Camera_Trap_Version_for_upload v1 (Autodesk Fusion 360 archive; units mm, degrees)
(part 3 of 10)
sketch "Sketch1" plane through (0, 50, 0) normal (0, 1, 0) x axis (-1, 0, 0)
  line L1 (19, 40.6) -> (11, 40.6)
  line L2 (19, 163.6063) -> (19, 40.6)
  line L3 (32, 163.6063) -> (19, 163.6063)
  line L4 (37, 215) -> (37, 168.6063)
  line L5 (30, 215) -> (37, 215)
  line L6 (30, 175.6063) -> (30, 215)
  line L7 (11, 170.6063) -> (25, 170.6063)
  line L8 (11, 40.6) -> (11, 170.6063)
  line L9 (37, 215) -> (37, 168.6063)
  line L10 (32, 163.6063) -> (19, 163.6063)
  line L11 (19, 40.6) -> (19, 163.6063)
  line L12 (-126.7143, 211.7174) -> (-122, 215)
  line L13 (-129, 215) -> (-126.7143, 211.7174)
  line L14 (19, 215) -> (-129, 215)
  line L15 (19, 40.6) -> (19, 215)
  line L16 (-129, 40.6) -> (19, 40.6)
  line L17 (-129, 215) -> (-129, 40.6)
  line L18 (19, 215) -> (37, 215)
  line L19 (19, 163.6063) -> (19, 215)
  line L20 (37, 168.6018) -> (37, 215)
  line L21 (19, 163.6063) -> (31.9982, 163.6018)
  line L22 (-102.2935, 219) -> (-102.2935, 215)
  arc A1 centre (32, 168.6063) radius 5 clockwise from (37, 168.6063) to (32, 163.6063)
  arc A2 centre (25, 175.6063) radius 5 clockwise from (30, 175.6063) to (25, 170.6063)
  arc A3 centre (32, 168.6063) radius 5 clockwise from (37, 168.6063) to (32, 163.6063)
  arc A4 centre (32, 168.6018) radius 5 clockwise from (37, 168.6018) to (31.9982, 163.6018)
  point P20 (19, 40.6)
  point P25 (19, 40.6)
  point P8 (37, 215)
  point P27 (37, 215)
  point P28 (19, 215)
  point P4 (19, 163.6063)
  point P29 (19, 163.6063)
  point P30 (37, 163.6)
  point P34 (-102.2935, 215)
  point P22 (-126.7143, 211.7174)
  point P23 (-129, 215)
  point P35 (-102.2935, 219)
  perpendicular L12 L13
  horizontal L14
  vertical L15
  horizontal L16
  vertical L17
  coincident P20 P25
  coincident P8 P27
  coincident L15 P28
  perpendicular L15 L18
  coincident P4 P29
  perpendicular L18 L20
  coincident P30 L20
  coincident P30 L21
  tangent L20 A4
  tangent L21 A4
  coincident L14 P34
  perpendicular L14 L22
  dimension "d509" distance P22 P23 = 4
  dimension "d510" distance P27 P30 = 51.4
  dimension "d511" radius A4 = 5
  dimension "d514" distance P34 P35 = 4
extrude "Extrude1" new body sketch "Sketch1" profile of L1 L2 L3 L5 L6 A2 L7 L8 L9 A3 L11 L14 L15 L16 L17 L18 L19 L20 along normal blind 7
sketch "Sketch1" plane through (129, 0, 0) normal (1, 0, 0) x axis (0, 1, 0)
  line L1 (50, 40.6) -> (50, 215)
  line L2 (57, 40.6) -> (50, 40.6)
  line L3 (57, 215) -> (57, 40.6)
  line L4 (50, 215) -> (57, 215)
  line L5 (0, 220) -> (0, 40)
  line L6 (-50, 170.6) -> (-50, 60.6)
  line L7 (-30, 40.6) -> (50, 40.6)
  line L8 (57, 40.6) -> (57, 215)
  line L9 (57, 40.6) -> (50, 40.6)
  line L10 (50, 215) -> (-50, 215)
  line L11 (-50, 215) -> (-50, 175.6063)
  line L12 (-50, 170.6063) -> (-50, 175.6063)
  line L13 (-25, 40.6) -> (57, 40.6)
  line L14 (-50, 220.6) -> (-50, 65.6)
  line L15 (57, 220.6) -> (-50, 220.6)
  line L16 (57, 40.6) -> (57, 220.6)
  line L17 (15, 95.6) -> (-15, 95.6)
  line L18 (25, 55.6) -> (25, 85.6)
  line L19 (-15, 45.6) -> (15, 45.6)
  line L20 (-25, 85.6) -> (-25, 55.6)
  circle C1 centre (0, 195.4) radius 20
  arc A1 centre (-30, 60.6) radius 20 clockwise from (-30, 40.6) to (-50, 60.6)
  arc A2 centre (-25, 65.6) radius 25 clockwise from (-25, 40.6) to (-50, 65.6)
  circle C2 centre (0, 70.6) radius 11
  arc A3 centre (-15, 85.6) radius 10 clockwise from (-25, 85.6) to (-15, 95.6)
  arc A4 centre (15, 85.6) radius 10 clockwise from (15, 95.6) to (25, 85.6)
  arc A5 centre (15, 55.6) radius 10 clockwise from (25, 55.6) to (15, 45.6)
  arc A6 centre (-15, 55.6) radius 10 clockwise from (-15, 45.6) to (-25, 55.6)
  point P4 (57, 40.6)
  point P21 (57, 40.6)
  point P23 (57, 220.6)
  vertical L5
  horizontal L13
  vertical L14
  horizontal L15
  vertical L16
  coincident P4 P21
  tangent L13 A2
  tangent L14 A2
  dimension "d515" distance P21 P23 = 180
  dimension "d516" radius A2 = 25
extrude "Extrude1" new body sketch "Sketch1" profile of L1 L2 L3 L4 C1 L6 L7 L8 L9 L10 L11 L12 L13 L14 L15 L16 A2 along normal blind 7
extrude "Extrude7" cut of existing geometry blind -7
sketch "Sketch2" plane through (-5, 0, 0) normal (1, 0, 0) x axis (0, 1, 0)
  circle C1 centre (0, 70.6) radius 11.1
  circle C2 centre (0, 70.6) radius 13.1
extrude "Extrude3" cut of existing geometry blind -10
extrude "Extrude4" cut sketch "Sketch1" profile of C8 C9 C10 C11 against normal blind 10
combine "Combine1"
sketch "Sketch1" plane through (0, -50, 0) normal (0, -1, 0) x axis (1, 0, 0)
  line L1 (129, 65.6) -> (129, 220.6)
  line L2 (136, 65.6) -> (129, 65.6)
  line L3 (136, 220.6) -> (136, 65.6)
  line L4 (129, 220.6) -> (136, 220.6)
  line L5 (-14, 139) -> (-19, 139)
  line L6 (-14, 129) -> (-14, 139)
  line L7 (-19, 129) -> (-14, 129)
  line L8 (-19, 139) -> (-19, 129)
  line L9 (131, 139) -> (131, 129)
  line L10 (131, 129) -> (136, 129)
  line L11 (136, 129) -> (136, 139)
  line L12 (136, 139) -> (131, 139)
  horizontal L5
  vertical L6
  horizontal L7
  vertical L8
  horizontal L12
  vertical L11
  horizontal L10
  vertical L9
extrude "Extrude1" new body sketch "Sketch1" profile of L3 L5 L6 L7 L8 L9 L10 L11 L12 along normal blind 8
chamfer "Chamfer1" distance 1
chamfer "Chamfer2" distance 1
combine "Combine1"
fillet "Fillet1" radius 10
fillet "Fillet2" radius 10
sketch "Sketch1" plane through (0, -50, 0) normal (0, -1, 0) x axis (1, 0, 0)
  line L1 (-19, 129) -> (-14, 129)
  line L2 (-19, 60.6) -> (-19, 129)
  line L3 (-11, 60.6) -> (-19, 60.6)
  line L4 (-11, 170.6063) -> (-11, 60.6)
  line L5 (-25, 170.6063) -> (-11, 170.6063)
  line L6 (-30, 215) -> (-30, 175.6063)
  line L7 (-37, 215) -> (-30, 215)
  line L8 (-37, 168.6063) -> (-37, 215)
  line L9 (-19, 163.6063) -> (-32, 163.6063)
  line L10 (-19, 139) -> (-19, 163.6063)
  line L11 (-14, 139) -> (-19, 139)
  line L12 (-14, 129) -> (-14, 139)
  line L13 (131, 129) -> (136, 129)
  line L14 (131, 139) -> (131, 129)
  line L15 (136, 139) -> (131, 139)
  line L16 (136, 220.6) -> (136, 139)
  line L17 (129, 220.6) -> (136, 220.6)
  line L18 (129, 65.6) -> (129, 220.6)
  line L19 (136, 65.6) -> (129, 65.6)
  line L20 (136, 129) -> (136, 65.6)
  line L21 (141.4511, 160) -> (-25, 160)
  line L22 (141.4511, 105) -> (141.4511, 160)
  line L23 (-25, 105) -> (141.4511, 105)
  line L24 (-25, 160) -> (-25, 105)
  line L25 (-13.6, 139) -> (-19, 139)
  line L26 (-13.6, 129) -> (-13.6, 139)
  line L27 (-19, 129) -> (-13.6, 129)
  line L28 (-19, 139) -> (-19, 129)
  line L29 (130.6, 139) -> (136, 139)
  line L30 (130.6, 129) -> (130.6, 139)
  line L31 (136, 129) -> (130.6, 129)
  line L32 (136, 139) -> (136, 129)
  line L33 (129, 160) -> (141.4511, 160)
  line L34 (125, 160) -> (141.4511, 160)
  arc A1 centre (-25, 175.6063) radius 5 clockwise from (-25, 170.6063) to (-30, 175.6063)
  arc A2 centre (-32, 168.6063) radius 5 clockwise from (-32, 163.6063) to (-37, 168.6063)
  point P16 (-19, 139)
  point P30 (-19, 139)
  point P21 (136, 139)
  point P34 (136, 139)
  point P38 (129, 160)
  point P39 (125, 160)
  point P40 (125, 160)
  point P41 (10, 160)
  point P31 (-13.6, 139)
  point P35 (130.6, 139)
  horizontal L21
  vertical L22
  horizontal L23
  vertical L24
  horizontal L25
  vertical L26
  horizontal L27
  vertical L28
  coincident P16 P30
  horizontal L29
  vertical L30
  horizontal L31
  vertical L32
  coincident P21 P34
  coincident L18 P38
  coincident L21 P38
  coincident L21 P39
  perpendicular L18 L34
  coincident P39 P40
  coincident L21 P41
  dimension "d535" distance P30 P31 = 5.4
  dimension "d536" distance P34 P35 = 5.4
extrude "Extrude1" new body sketch "Sketch1" profile of L1 L2 L4 L10 L11 L13 L15 L16 L18 L20 L21 L22 L23 L24 L25 L26 L27 L28 L29 L30 L31 L32 along normal blind 7 bodies "Front_wall"
fillet "Fillet1" radius 7
fillet "Fillet2" radius 7
copy_paste_bodies "CopyPasteBodies1"
copy_paste "CopyPaste10"
sketch "LL_pin" plane through (0, 0, 0) normal (0, 1, 0) x axis (1, 0, 0)
  line L1 (200, 0) -> (-200, 0)
  line L2 (0, -70) -> (0, 0)
  line L3 (-11, -70) -> (5, -70)
  line L4 (-11, -74.1) -> (-11, -70)
  line L5 (5, -70) -> (5, -74.1)
  line L6 (-5, -70) -> (-3, -70)
  line L7 (-5, -75) -> (-5, -74.1)
  line L8 (-3, -75) -> (-5, -75)
  line L9 (-3, -74.1) -> (-3, -75)
  line L10 (-5, -74.1) -> (-11, -74.1)
  line L11 (5, -74.1) -> (-3, -74.1)
  point P1 (0, 0)
  point P4 (0, 0)
  point P10 (-3, -70)
  point P2 (-200, 0)
  point P3 (200, 0)
  point P5 (0, -70)
  point P6 (5, -70)
  point P7 (-11, -70)
  point P9 (5, -74.1)
  point P11 (-5, -70)
  point P13 (-3, -75)
  horizontal L1
  coincident P1 P4
  perpendicular L1 L2
  horizontal L3
  vertical L4
  horizontal L10
  vertical L5
  horizontal L6
  vertical L7
  horizontal L8
  vertical L9
  midpoint L3 P10
  collinear L10 L11
  dimension "d120_4" distance P2 P3 = 400
  dimension "d122_4" distance P4 P5 = 70
  dimension "d123_4" distance P6 P7 = 16 (= "LL_Pin_Length")
  dimension "d124_4" distance P6 P9 = 4.1 (= "LL_Pin_half_height")
  dimension "d129_4" distance P10 P11 = 2 (= "LL_lip_length")
  dimension "d130_4" distance P10 P13 = 5 (= "LL_lip_half_height")
revolve "Revolve1" sketch "LL_pin" AlongAngle 360 named "d131_4" bodies "S1_L_Pin"
sketch "LL_pin_falt_face" plane through (5, 0, 0) normal (1, 0, 0) x axis (0, 1, 0)
  line L1 (0, 67) -> (0, 70)
  line L2 (2.8039, 67.0087) -> (-2.8039, 67.0087)
  circle C1 centre (0, 70) radius 4.1
  point P2 (0, 70)
  point P3 (0, 70)
  point P5 (-2.8039, 67.0087)
  point P6 (2.8039, 67.0087)
  coincident P2 P3
  vertical L1
  coincident C1 P5
  coincident C1 P6
  perpendicular L1 L2
extrude "Extrude1" cut sketch "LL_pin_falt_face" profile of C1 L2 against normal blind 5 named "d132_4"
fillet "Fillet1" radius 1 named "d135_3"
position "Position12"
position "Position13"
extrude "Extrude2" add of existing geometry blind 67
work_plane "WorkPlane1" RotateAngle 0
sketch "Sketch5" plane through (0, 0, 0) normal (0, 1, 0) x axis (1, 0, 0)
  line L1 (-78, -74.1) -> (-78, -65.9)
  line L2 (0, -67.0087) -> (0, -65.9)
  line L3 (5, -67.0087) -> (0, -67.0087)
  line L4 (5, -74.1) -> (5, -67.0087)
  line L5 (-5, -65.9) -> (-5, -65)
  line L6 (-5, -75) -> (-5, -74.1)
  line L7 (-2.005, -65.9) -> (0, -65.9)
  line L8 (-2.005, -74.1) -> (5, -74.1)
  line L9 (-5, -65) -> (-3, -65)
  line L10 (-5, -75) -> (-3, -75)
  line L11 (-78, -65.9) -> (-5, -65.9)
  line L12 (-78, -74.1) -> (-5, -74.1)
  line L13 (-41, -75) -> (-5, -75)
  line L14 (-63, -75) -> (-41, -75)
  line L15 (-68, -75) -> (-63, -75)
  line L16 (-41, -75) -> (-63, -75)
  line L17 (-41, -65) -> (-41, -75)
  line L18 (-63, -65) -> (-41, -65)
  line L19 (-63, -75) -> (-63, -65)
  line L20 (-73, -75) -> (-74, -75)
  line L21 (-73, -65) -> (-73, -75)
  line L22 (-74, -65) -> (-73, -65)
  line L23 (-74, -75) -> (-74, -65)
  arc A1 centre (-2.005, -75.1) radius 1 clockwise from (-3, -75) to (-2.005, -74.1)
  arc A2 centre (-2.005, -64.9) radius 1 clockwise from (-2.005, -65.9) to (-3, -65)
  point P11 (-5, -75)
  point P18 (-5, -75)
  point P19 (-41, -75)
  point P20 (-63, -75)
  point P21 (-68, -75)
  point P25 (-74, -75)
  point P26 (-73, -75)
  coincident P11 P18
  perpendicular L6 L13
  parallel L12 L14
  parallel L14 L15
  horizontal L16
  vertical L17
  horizontal L18
  vertical L19
  horizontal L20
  vertical L21
  horizontal L22
  vertical L23
  dimension "d546" distance P18 P19 = 36
  dimension "d547" distance P19 P20 = 22
  dimension "d548" distance P20 P21 = 5
  dimension "d549" distance P25 P26 = 1
extrude "Extrude3" cut sketch "Sketch5" profile of L11 L12 L17 L18 L19 distance 0.5
revolve "Revolve2" sketch "Sketch5" AlongAngle 360
sketch "Roll_holders" plane through (0, 0, 0) normal (0, 1, 0) x axis (1, 0, 0)
  curve K1 (-18.5, -200.1) -> (-16.5, -200.1)
  curve K2 (-16.5, -191.9) -> (-18.5, -191.9)
  line L1 (-21, -200.1) -> (-21, -191.9)
  line L2 (5, -193.0087) -> (-3, -193.0087)
  line L3 (5, -200.1) -> (5, -193.0087)
  line L4 (-5, -191.9) -> (-5, -191)
  line L5 (-5, -201) -> (-5, -200.1)
  line L6 (-5, -191) -> (-3, -191)
  line L7 (-5, -201) -> (-3, -201)
  line L8 (-16.5, -191.9) -> (-5, -191.9)
  line L9 (-21, -191.9) -> (-18.5, -191.9)
  line L10 (-16.5, -200.1) -> (-5, -200.1)
  line L11 (-21, -200.1) -> (-18.5, -200.1)
  line L12 (0, -227.8815) -> (0, -227.7827)
  line L13 (0, -227.7827) -> (0, -227.4397)
  line L14 (0, -227.4397) -> (0, -227.2429)
  line L15 (0, -227.2429) -> (0, -226.6752)
  line L16 (0, -227.9963) -> (0, -227.8815)
  line L17 (0, -228) -> (0, -227.9963)
  line L18 (0, -164.0037) -> (0, -164)
  line L19 (0, -164.0037) -> (0, -164.1185)
  line L20 (0, -164.2173) -> (0, -164.1185)
  line L21 (0, -164.2173) -> (0, -164.5603)
  line L22 (0, -164.7571) -> (0, -164.5603)
  line L23 (0, -164.7571) -> (0, -165.3248)
  line L24 (0, -165.6174) -> (0, -165.3248)
  line L25 (0, -165.6174) -> (0, -166.4041)
  line L26 (0, -166.7895) -> (0, -166.4041)
  line L27 (0, -166.7895) -> (0, -167.787)
  line L28 (0, -168.2613) -> (0, -167.787)
  line L29 (0, -168.2613) -> (0, -169.4595)
  line L30 (0, -170.0178) -> (0, -169.4595)
  line L31 (0, -170.0178) -> (0, -171.4042)
  line L32 (0, -172.0409) -> (0, -171.4042)
  line L33 (0, -172.0409) -> (0, -173.6014)
  line L34 (0, -174.3098) -> (0, -173.6014)
  line L35 (0, -174.3098) -> (0, -176.0032)
  line L36 (0, -176.0032) -> (0, -176.0038)
  line L37 (0, -176.0038) -> (0, -176.0284)
  line L38 (0, -176.8013) -> (0, -176.0284)
  line L39 (0, -176.8013) -> (0, -178.3701)
  line L40 (0, -178.3701) -> (0, -178.3707)
  line L41 (0, -178.3707) -> (0, -178.5249)
  line L42 (0, -178.6604) -> (0, -178.5249)
  line L43 (0, -179.4899) -> (0, -178.6604)
  line L44 (0, -179.4899) -> (0, -180.918)
  line L45 (0, -180.918) -> (0, -180.9184)
  line L46 (0, -180.9184) -> (0, -181.0503)
  line L47 (0, -181.4703) -> (0, -181.0503)
  line L48 (0, -182.3478) -> (0, -181.4703)
  line L49 (0, -182.3478) -> (0, -183.6205)
  line L50 (0, -183.6205) -> (0, -183.6209)
  line L51 (0, -183.6209) -> (0, -183.7292)
  line L52 (0, -184.4292) -> (0, -183.7292)
  line L53 (0, -185.3458) -> (0, -184.4292)
  line L54 (0, -185.3458) -> (0, -186.4501)
  line L55 (0, -186.4501) -> (0, -186.4504)
  line L56 (0, -186.4504) -> (0, -186.534)
  line L57 (0, -187.4694) -> (0, -186.534)
  line L58 (0, -187.507) -> (0, -187.4694)
  line L59 (0, -188.4532) -> (0, -187.507)
  line L60 (0, -188.4532) -> (0, -189.3777)
  line L61 (0, -189.3777) -> (0, -189.3779)
  line L62 (0, -189.3779) -> (0, -189.4359)
  line L63 (0, -190.5109) -> (0, -189.4359)
  line L64 (0, -190.6718) -> (0, -190.5109)
  line L65 (0, -191.6379) -> (0, -190.6718)
  line L66 (0, -191.6379) -> (0, -192.3733)
  line L67 (0, -192.3733) -> (0, -192.3734)
  line L68 (0, -192.3734) -> (0, -192.4051)
  line L69 (0, -193.5524) -> (0, -192.4051)
  line L70 (0, -193.8913) -> (0, -193.5524)
  line L71 (0, -194.8675) -> (0, -193.8913)
  line L72 (0, -194.8675) -> (0, -195.4061)
  line L73 (0, -195.4061) -> (0, -195.4061)
  line L74 (0, -195.4061) -> (0, -195.4113)
  line L75 (0, -196.5887) -> (0, -195.4113)
  line L76 (0, -196.5939) -> (0, -196.5887)
  line L77 (0, -196.5939) -> (0, -196.5939)
  line L78 (0, -197.1325) -> (0, -196.5939)
  line L79 (0, -198.1087) -> (0, -197.1325)
  line L80 (0, -198.1087) -> (0, -198.4476)
  line L81 (0, -199.5949) -> (0, -198.4476)
  line L82 (0, -199.6266) -> (0, -199.5949)
  line L83 (0, -199.6267) -> (0, -199.6266)
  line L84 (0, -200.3621) -> (0, -199.6267)
  line L85 (0, -201.3282) -> (0, -200.3621)
  line L86 (0, -201.3282) -> (0, -201.4891)
  line L87 (0, -202.5641) -> (0, -201.4891)
  line L88 (0, -202.6221) -> (0, -202.5641)
  line L89 (0, -202.6223) -> (0, -202.6221)
  line L90 (0, -203.5468) -> (0, -202.6223)
  line L91 (0, -204.493) -> (0, -203.5468)
  line L92 (0, -204.493) -> (0, -204.5306)
  line L93 (0, -205.466) -> (0, -204.5306)
  line L94 (0, -205.5496) -> (0, -205.466)
  line L95 (0, -205.5499) -> (0, -205.5496)
  line L96 (0, -206.6542) -> (0, -205.5499)
  line L97 (0, -207.5708) -> (0, -206.6542)
  line L98 (0, -208.2708) -> (0, -207.5708)
  line L99 (0, -208.3791) -> (0, -208.2708)
  line L100 (0, -208.3795) -> (0, -208.3791)
  line L101 (0, -209.6522) -> (0, -208.3795)
  line L102 (0, -210.5297) -> (0, -209.6522)
  line L103 (0, -210.9497) -> (0, -210.5297)
  line L104 (0, -211.0816) -> (0, -210.9497)
  line L105 (0, -211.082) -> (0, -211.0816)
  line L106 (0, -212.5101) -> (0, -211.082)
  line L107 (0, -213.3396) -> (0, -212.5101)
  line L108 (0, -213.4751) -> (0, -213.3396)
  line L109 (0, -213.6293) -> (0, -213.4751)
  line L110 (0, -213.6299) -> (0, -213.6293)
  line L111 (0, -215.1987) -> (0, -213.6299)
  line L112 (0, -215.9716) -> (0, -215.1987)
  line L113 (0, -215.9962) -> (0, -215.9716)
  line L114 (0, -215.9968) -> (0, -215.9962)
  line L115 (0, -217.6902) -> (0, -215.9968)
  line L116 (0, -218.3986) -> (0, -217.6902)
  line L117 (0, -219.9591) -> (0, -218.3986)
  line L118 (0, -220.5958) -> (0, -219.9591)
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  point P279 (6, -196)
  point P283 (21, -196)
  point P285 (6, -216)
  point P280 (21, -196)
  point P286 (26, -196)
  point P288 (21, -211)
  point P287 (26, -211)
  point P289 (44.1262, -202.5476)
  point P292 (122, -196)
  point P293 (117, -196)
  point P295 (122, -211)
  point P294 (117, -211)
  point P296 (98.8738, -202.5477)
  point P298 (127, -196)
  point P300 (122, -216)
  dimension "d335_1" distance P279 P283 = 15
  dimension "d336_1" distance P279 P285 = 20
  dimension "d337_1" distance P280 P286 = 5
  dimension "d338_1" distance P280 P288 = 15
  dimension "d339_1" angle = 25
  dimension "d340_1" distance P287 P289 = 20
  dimension "d342_1" distance P283 P292 = 101
  dimension "d343_1" distance P292 P293 = 5
  dimension "d344_1" distance P292 P295 = 15
  dimension "d345_1" angle = 155
  dimension "d346_1" distance P294 P296 = 20
  dimension "d347_1" distance P292 P298 = 5
  dimension "d348_1" distance P292 P300 = 20
revolve "Revolve1" sketch "Roll_holders" AlongAngle 360 named "d341_1"
position "Position14"
extrude "Extrude1" add of existing geometry blind 3
sketch "LL_pin" plane through (0, 0, 0) normal (0, 1, 0) x axis (1, 0, 0)
  line L1 (200, 0) -> (-200, 0)
  line L2 (0, -70) -> (0, 0)
  line L3 (-11, -70) -> (5, -70)
  line L4 (-11, -74.1) -> (-11, -70)
  line L5 (5, -70) -> (5, -74.1)
  line L6 (-5, -70) -> (-3, -70)
  line L7 (-5, -75) -> (-5, -74.1)
  line L8 (-3, -75) -> (-5, -75)
  line L9 (-3, -74.1) -> (-3, -75)
  line L10 (-5, -74.1) -> (-11, -74.1)
  line L11 (5, -74.1) -> (-3, -74.1)
  point P1 (0, 0)
  point P4 (0, 0)
  point P10 (-3, -70)
  point P2 (-200, 0)
  point P3 (200, 0)
  point P5 (0, -70)
  point P6 (5, -70)
  point P7 (-11, -70)
  point P9 (5, -74.1)
  point P11 (-5, -70)
  point P13 (-3, -75)
  horizontal L1
  coincident P1 P4
  perpendicular L1 L2
  horizontal L3
  vertical L4
  horizontal L10
  vertical L5
  horizontal L6
  vertical L7
  horizontal L8
  vertical L9
  midpoint L3 P10
  collinear L10 L11
  dimension "d120_5" distance P2 P3 = 400
  dimension "d122_5" distance P4 P5 = 70
  dimension "d123_5" distance P6 P7 = 16 (= "LL_Pin_Length")
  dimension "d124_5" distance P6 P9 = 4.1 (= "LL_Pin_half_height")
  dimension "d129_5" distance P10 P11 = 2 (= "LL_lip_length")
  dimension "d130_5" distance P10 P13 = 5 (= "LL_lip_half_height")
revolve "Revolve1" sketch "LL_pin" AlongAngle 360 named "d131_5" bodies "S1_L_Pin"
sketch "LL_pin_falt_face" plane through (5, 0, 0) normal (1, 0, 0) x axis (0, 1, 0)
  line L1 (0, 67) -> (0, 70)
  line L2 (2.8039, 67.0087) -> (-2.8039, 67.0087)
  circle C1 centre (0, 70) radius 4.1
  point P2 (0, 70)
  point P3 (0, 70)
  point P5 (-2.8039, 67.0087)
  point P6 (2.8039, 67.0087)
  coincident P2 P3
  vertical L1
  coincident C1 P5
  coincident C1 P6
  perpendicular L1 L2
extrude "Extrude1" cut sketch "LL_pin_falt_face" profile of C1 L2 against normal blind 5 named "d132_5"
fillet "Fillet1" radius 1 named "d135_4"
sketch "paper_holder" plane through (0, 0, 0) normal (0, 1, 0) x axis (1, 0, 0)
  line L1 (16, -74.1) -> (16, -77.5)
  line L2 (11, -74.1) -> (16, -74.1)
  line L3 (11, -70) -> (11, -74.1)
  line L4 (127, -75) -> (129, -75)
  line L5 (127, -77.5) -> (127, -75)
  line L6 (16, -77.5) -> (127, -77.5)
  line L7 (135, -74.1) -> (135, -70)
  line L8 (129, -74.1) -> (135, -74.1)
  line L9 (129, -75) -> (129, -74.1)
  line L10 (150, -70) -> (140, -70)
  line L11 (135, -70) -> (11, -70)
  line L12 (21, -74.1) -> (16, -74.1)
  line L13 (122, -69) -> (122, -71)
  line L14 (21, -71) -> (21, -69)
  line L15 (122, -80) -> (21, -80)
  line L16 (122, -62.5) -> (122, -80)
  line L17 (21, -62.5) -> (122, -62.5)
  line L18 (21, -80) -> (21, -62.5)
  point P2 (16, -77.5)
  point P3 (16, -74.1)
  point P4 (11, -74.1)
  point P5 (129, -75)
  point P6 (127, -75)
  point P7 (127, -77.5)
  point P15 (21, -71)
  point P16 (122, -71)
  point P19 (21, -80)
  point P20 (122, -80)
  point P22 (21, -62.5)
  vertical L1
  perpendicular L1 L2
  perpendicular L2 L3
  perpendicular L4 L5
  parallel L8 L10
  perpendicular L1 L12
  vertical L13
  vertical L14
  horizontal L15
  vertical L16
  horizontal L17
  vertical L18
  dimension "d146_2" distance P2 P3 = 3.4
  dimension "d147_2" distance P3 P4 = 5
  dimension "d154_2" distance P5 P6 = 2
  dimension "d155_2" distance P6 P7 = 2.5
  dimension "d164_2" distance P15 P16 = 101
  dimension "d167_2" distance P19 P20 = 101
  dimension "d168_2" distance P19 P22 = 17.5
move "Move2"
sketch "Sketch5" plane through (486.5, 0, 0) normal (1, 0, 0) x axis (0, 1, 0)
  line L1 (0.1129, -15.3996) -> (0.1129, -17.3996)
  line L2 (8.1247, -15.3996) -> (0.1129, -15.3996)
  line L3 (-8.1247, -15.3996) -> (0.1129, -15.3996)
  circle C1 centre (0, 0.1) radius 4.1
  circle C2 centre (0, 0.1) radius 17.5
  point P3 (0.1129, -17.3996)
  point P5 (8.1247, -15.3996)
  point P6 (-8.1247, -15.3996)
  point P4 (0.1129, -15.3996)
  coincident C2 P3
  vertical L1
  coincident C2 P5
  perpendicular L1 L2
  coincident C2 P6
  perpendicular L1 L3
  dimension "d560" distance P3 P4 = 2
copy_paste_bodies "CopyPasteBodies2"
move "Move2"
move "Move3"
sketch "LL_pin" plane through (0, 0, 0) normal (0, 1, 0) x axis (1, 0, 0)
  line L1 (200, 0) -> (-200, 0)
  line L2 (0, -70) -> (0, 0)
  line L3 (-11, -70) -> (5, -70)
  line L4 (-11, -74.1) -> (-11, -70)
  line L5 (-5, -70) -> (-3, -70)
  line L6 (-5, -75) -> (-5, -74.1)
  line L7 (-4, -75) -> (-5, -75)
  line L8 (-5, -74.1) -> (-11, -74.1)
  line L9 (5, -74.1) -> (-1, -74.1)
  line L10 (-3, -75) -> (-3, -74.1)
  line L11 (-2, -74.1) -> (-1, -74.1)
  line L12 (-4, -83) -> (-2, -83)
  line L13 (-4, -75) -> (-4, -83)
  line L14 (-2, -74.1) -> (-2, -83)
  line L15 (7, -74.1) -> (5, -74.1)
  line L16 (7, -70) -> (7, -74.1)
  line L17 (5, -70) -> (7, -70)
  point P1 (0, 0)
  point P4 (0, 0)
  point P10 (-3, -70)
  point P2 (-200, 0)
  point P3 (200, 0)
  point P5 (0, -70)
  point P6 (5, -70)
  point P7 (-11, -70)
  point P9 (5, -74.1)
  point P11 (-5, -70)
  point P13 (-3, -75)
  horizontal L1
  coincident P1 P4
  perpendicular L1 L2
  horizontal L3
  vertical L4
  horizontal L8
  horizontal L5
  vertical L6
  horizontal L7
  midpoint L3 P10
  collinear L8 L9
  perpendicular L7 L10
  parallel L9 L11
  horizontal L12
  perpendicular L11 L14
  perpendicular L15 L16
  dimension "d120_3_1_1" distance P2 P3 = 400
  dimension "d122_3_1_1" distance P4 P5 = 70
  dimension "d123_3_1_1" distance P6 P7 = 16 (= "LL_Pin_Length")
  dimension "d124_3_1_1" distance P6 P9 = 4.1 (= "LL_Pin_half_height")
  dimension "d129_3_1_1" distance P10 P11 = 2 (= "LL_lip_length")
  dimension "d130_3_1_1" distance P10 P13 = 5 (= "LL_lip_half_height")
revolve "Revolve1" sketch "LL_pin" AlongAngle 360 named "d131_3_1_1" bodies "S2_L_Pin"
sketch "LL_pin_falt_face" plane through (5, 0, 0) normal (1, 0, 0) x axis (0, 1, 0)
  line L1 (0, 67) -> (0, 70)
  line L2 (2.8039, 67.0087) -> (-2.8039, 67.0087)
  circle C1 centre (0, 70) radius 4.1
  point P2 (0, 70)
  point P3 (0, 70)
  point P5 (-2.8039, 67.0087)
  point P6 (2.8039, 67.0087)
  coincident P2 P3
  vertical L1
  coincident C1 P5
  coincident C1 P6
  perpendicular L1 L2
extrude "Extrude1" cut sketch "LL_pin_falt_face" profile of C1 L2 against normal blind 5 named "d132_3_1_1"
position "Position16"
position "Position17"
extrude "Extrude2" add of existing geometry blind 2
extrude "Extrude3" cut sketch "LL_pin_falt_face" profile of C1 L2 along normal blind 2
fillet "Fillet2" radius 1
position "Position18"
extrude "Extrude2" add of existing geometry blind 2
extrude "Extrude3" add of existing geometry blind 2
move "Move4"
position "Position19"
extrude "Extrude1" add of existing geometry blind 2
move "Move1"
extrude "Extrude2" add of existing geometry blind 2
sketch "Sketch6" plane through (-4, 0, 0) normal (1, 0, 0) x axis (0, 1, 0)
  circle C1 centre (0, 70.6) radius 4.1
  circle C2 centre (0, 70.6) radius 13
  circle C3 centre (0, 70.6) radius 17.5
  circle C4 centre (0, 70.6) radius 6.5
  circle C5 centre (0, 70.6) radius 16
  concentric C1 C3
  concentric C3 C4
  concentric C4 C5
  dimension "d584" diameter C3 = 35
  dimension "d585" diameter C4 = 13
  dimension "d589" diameter C5 = 32
extrude "Extrude9" new body sketch "Sketch6" profile of C2 C3 C4 blind 2 from offset 1 bodies "Restraining_Cap"
extrude "Extrude10" add sketch "Sketch6" profile of C3 C5 blind -14 from offset 2
move "Move1"
move "Move5"
move "Move2"
position "Position20"
sketch "Slidingcap" plane through (-5, 0, 0) normal (1, 0, 0) x axis (0, 1, 0)
  line L1 (12.7, 143.2) -> (0, 143.2)
  line L2 (12.7, 133.2) -> (12.7, 143.2)
  line L3 (11.2, 143.2) -> (11.2, 133.2)
  line L4 (-12.7, 133.2) -> (-12.7, 143.2)
  line L5 (-11.2, 143.2) -> (-11.2, 133.2)
  line L6 (6.5, 133.2) -> (6.5, 143.2)
  line L7 (-6.5, 133.2) -> (-6.5, 143.2)
  line L8 (11.0982, 133.2) -> (11.2, 133.2)
  circle C1 centre (0, 133) radius 4.1
  arc A1 centre (0, 143.2) radius 12.7 clockwise from (10.7309, 136.4075) to (10.6186, 136.2333)
  arc A2 centre (0, 143.2) radius 12.7 clockwise from (-12.7, 143.2) to (12.7, 143.2)
  arc A3 centre (0, 143.2) radius 12.7 clockwise from (-10.6186, 136.2333) to (-10.7309, 136.4075)
  arc A4 centre (0, 133.2) radius 11.2 clockwise from (11.2, 133.2) to (-11.2, 133.2)
  arc A5 centre (0, 143.2) radius 11.2 clockwise from (-11.2, 143.2) to (11.2, 143.2)
  arc A6 centre (0, 133.2) radius 6.5 clockwise from (6.5, 133.2) to (-6.5, 133.2)
  arc A7 centre (0, 143.2) radius 6.5 clockwise from (-6.5, 143.2) to (6.5, 143.1986)
  arc A8 centre (0, 133.2) radius 12.7 clockwise from (12.7, 133.2) to (-12.7, 133.2)
  point P4 (0, 143.2)
  point P7 (0, 143.2)
  point P14 (-11.2, 133.2)
  point P23 (6.5, 143.2)
  point P24 (6.5, 133.2)
  point P26 (-6.5, 133.2)
  point P27 (6.5, 143.1986)
  point P3 (0, 133.2)
  concentric A2 A7
  concentric A5 A7
  coincident P4 P7
  horizontal L1
  horizontal L8
  coincident P14 L8
  concentric A1 A2
  concentric A2 A3
  coincident L1 P23
  coincident P24 L8
  tangent L6 A6
  coincident P26 L8
  tangent L7 A6
  coincident L6 P27
  dimension "d594" diameter A6 = 13
  dimension "d596" distance P3 P4 = 10
  dimension "d597" diameter A7 = 13
  dimension "d598" diameter A2 = 25.4 (= "Radius_slidder + 3 mm")
  dimension "d619" diameter A5 = 22.4 (= "Radius_slidder")
revolve "Revolve1" sketch "paper_holder" AlongAngle 360 named "d159_2" bodies "S1_paper_holder"
sketch "cutting_Base" plane through (127, 0, 0) normal (1, 0, 0) x axis (0, 1, 0)
  line L1 (2.3976, 62.8936) -> (-2.3976, 62.8936)
  circle C1 centre (0, 70) radius 5
  circle C2 centre (0, 70) radius 7.5
  point P3 (-2.3976, 62.8936)
  point P4 (2.3976, 62.8936)
  coincident C2 P3
  coincident C2 P4
  horizontal L1
extrude "Extrude1" cut sketch "cutting_Base" profile of C2 L1 against normal blind 110.1 named "d160_2"
extrude "Extrude3" cut sketch "paper_holder" profile of L6 L11 L13 L14 L15 L16 L17 L18 distance 1 named "d169_2"
remove_instance "RemoveInstance1"
sketch "flat_front_pin_base" plane through (11, 0, 0) normal (-1, 0, 0) x axis (0, -1, 0)
  line L1 (0, 70) -> (0, 74.1)
  line L2 (0, 67) -> (0, 70)
  line L3 (2.7971, 67.0023) -> (-2.7971, 67.0023)
  circle C1 centre (0, 70) radius 4.1
  point P3 (0, 74.1)
  point P2 (0, 70)
  point P4 (0, 70)
  point P5 (0, 70)
  point P7 (-2.7971, 67.0023)
  point P8 (2.7971, 67.0023)
  point P6 (0, 67)
  coincident C1 P3
  coincident P2 P4
  vertical L1
  coincident P2 P5
  parallel L1 L2
  coincident C1 P7
  coincident C1 P8
  horizontal L3
  dimension "d175_2" distance P5 P6 = 3
extrude "Extrude4" cut sketch "flat_front_pin_base" profile of C1 against normal blind 5 named "d173_2"
offset_faces "OffsetFaces1" distance -0.1 named "d179_1"
position "Position15"
extrude "Extrude1" new body sketch "Slidingcap" profile of A8 A4 A3 A5 L2 L3 L4 L5 against normal blind 7 bodies "Sliding_cap"
extrude "Extrude2" add sketch "Slidingcap" profile of C1 A8 A6 A4 A7 A3 A5 L2 L3 L4 L5 L6 L7 blind -2 from offset -7
extrude "Extrude3" cut sketch "Slidingcap" profile of C1 A6 A7 L6 L7 blind 1 from offset -6
extrude "Extrude4" cut sketch "Slidingcap" profile of C1 A6 A7 L6 L7 blind -1 from offset -7
extrude "Extrude28" new body sketch "Tests" profile of L68 L69 L70 L71 L72 L73 L74 L75 L76 L77 L78 L79 against normal blind 5
work_plane "WorkPlane1" AlongDistance 1
sketch "Sketch2" plane through (0, 51, 0) normal (0, 1, 0) x axis (1, 0, 0)
  line L1 (57.25, -152.0335) -> (47.25, -152.0335)
  line L2 (57.25, -113.9665) -> (57.25, -152.0335)
  line L3 (47.25, -113.9665) -> (57.25, -113.9665)
  line L4 (47.25, -152.0335) -> (47.25, -113.9665)
  line L5 (52.25, -113.9665) -> (52.25, -152.0335)
  line L6 (47.25, -133) -> (57.25, -133)
  line L7 (57.25, -113.9665) -> (47.25, -113.9665)
  line L8 (57.25, -152.0335) -> (57.25, -113.9665)
  line L9 (47.25, -152.0335) -> (57.25, -152.0335)
  line L10 (47.25, -113.9665) -> (47.25, -152.0335)
  line L11 (57.25, -152.0335) -> (47.25, -113.9665)
  line L12 (47.25, -152.0335) -> (57.25, -113.9665)
  line L13 (57.275, -113.9415) -> (47.225, -113.9415)
  line L14 (57.275, -152.0585) -> (57.275, -113.9415)
  line L15 (47.225, -152.0585) -> (57.275, -152.0585)
  line L16 (47.225, -113.9415) -> (47.225, -152.0585)
  line L17 (57.275, -162.1585) -> (57.275, -152.0585)
  line L18 (47.225, -162.1585) -> (57.275, -162.1585)
  line L19 (47.225, -152.0585) -> (47.225, -162.1585)
  line L20 (57.275, -113.9415) -> (47.225, -113.9415)
  line L21 (57.275, -162.1585) -> (57.275, -113.9415)
  line L22 (47.225, -162.1585) -> (57.275, -162.1585)
  line L23 (47.225, -113.9415) -> (47.225, -162.1585)
  line L24 (65.275, -170.1585) -> (65.275, -105.9415)
  line L25 (39.225, -170.1585) -> (65.275, -170.1585)
  line L26 (39.225, -105.9415) -> (39.225, -170.1585)
  line L27 (65.275, -105.9415) -> (39.225, -105.9415)
  point P6 (52.25, -152.0335)
  point P7 (52.25, -113.9665)
  point P8 (57.25, -133)
  point P9 (47.25, -133)
  point P14 (52.25, -133)
  point P5 (47.25, -113.9665)
  point P10 (47.25, -113.9665)
  point P17 (57.275, -152.0585)
  point P19 (57.275, -162.1585)
  point P20 (47.225, -162.1585)
  midpoint L1 P6
  midpoint L3 P7
  midpoint L2 P8
  midpoint L4 P9
  horizontal L7
  perpendicular L7 L8
  parallel L7 L9
  parallel L8 L10
  coincident L11 P14
  coincident L12 P14
  coincident P5 P10
  midpoint L5 P14
  perpendicular L15 L17
  perpendicular L17 L18
  horizontal L20
  vertical L21
  horizontal L22
  vertical L23
  dimension "d644" = -0.025
  dimension "d645" distance P17 P19 = 10.1
  dimension "d646" distance P19 P20 = 10.05
  dimension "d647" = -8
extrude "Extrude1" new body sketch "Sketch2" profile of L20 L21 L22 L23 L27 L26 L25 L24 along normal blind 10 bodies "Motor_holder_base"
move "Move1"
sketch "Sketch3" plane through (0, 41, 0) normal (0, -1, 0) x axis (1, 0, 0)
  line L1 (57.275, 162.1585) -> (47.225, 162.1585)
  line L2 (57.275, 113.9415) -> (57.275, 162.1585)
  line L3 (47.225, 113.9415) -> (57.275, 113.9415)
  line L4 (47.225, 162.1585) -> (47.225, 113.9415)
  line L5 (39.225, 105.9415) -> (39.225, 170.1585)
  line L6 (65.275, 105.9415) -> (39.225, 105.9415)
  line L7 (65.275, 170.1585) -> (65.275, 105.9415)
  line L8 (39.225, 170.1585) -> (65.275, 170.1585)
  line L9 (52.25, 105.9415) -> (52.25, 170.1585)
  line L10 (65.275, 138.05) -> (39.225, 138.05)
  line L11 (52.25, 152.1585) -> (52.25, 162.1585)
  line L12 (47.225, 137.2115) -> (47.225, 113.9415)
  line L13 (43.225, 137.2115) -> (47.225, 137.2115)
  line L14 (41.7344, 145.5025) -> (41.7344, 138.05)
  line L15 (44.7344, 145.5025) -> (44.7344, 138.05)
  line L16 (43.2344, 135.5025) -> (43.2344, 145.5025)
  line L17 (41.7344, 135.5025) -> (41.7344, 138.05)
  line L18 (44.7344, 135.5025) -> (44.7344, 138.05)
  line L19 (62.7656, 145.5025) -> (62.7656, 138.05)
  line L20 (59.7656, 145.5025) -> (59.7656, 138.05)
  line L21 (59.7656, 135.5025) -> (59.7656, 138.05)
  line L22 (62.7656, 135.5025) -> (62.7656, 138.05)
  arc A1 centre (43.2344, 135.5025) radius 1.5 clockwise from (44.7344, 135.5025) to (41.7344, 135.5025)
  arc A2 centre (43.2344, 145.5025) radius 1.5 clockwise from (41.7344, 145.5025) to (44.7344, 145.5025)
  arc A3 centre (61.2656, 145.5025) radius 1.5 clockwise from (59.7656, 145.5025) to (62.7656, 145.5025)
  arc A4 centre (61.2656, 135.5025) radius 1.5 clockwise from (62.7656, 135.5025) to (59.7656, 135.5025)
  circle C1 centre (43.2344, 145.5025) radius 1.5
  circle C2 centre (43.2344, 135.5025) radius 1.5
  circle C3 centre (61.2656, 145.5025) radius 1.5
  circle C4 centre (61.2656, 135.5025) radius 1.5
  point P10 (52.25, 170.1585)
  point P11 (52.25, 105.9415)
  point P12 (39.225, 138.05)
  point P13 (65.275, 138.05)
  point P14 (52.25, 162.1585)
  point P5 (47.225, 113.9415)
  point P16 (47.225, 113.9415)
  point P20 (41.7344, 138.05)
  point P22 (44.7344, 138.05)
  point P19 (43.2344, 145.5025)
  point P24 (43.2344, 145.5025)
  point P25 (43.2344, 135.5025)
  point P26 (43.2344, 135.5025)
  point P29 (62.7656, 138.05)
  point P21 (41.7344, 145.5025)
  point P30 (62.7656, 145.5025)
  point P33 (59.7656, 138.05)
  point P23 (44.7344, 145.5025)
  point P32 (59.7656, 145.5025)
  point P27 (41.7344, 135.5025)
  point P36 (62.7656, 135.5025)
  point P28 (44.7344, 135.5025)
  point P34 (59.7656, 135.5025)
  point P15 (52.25, 152.1585)
  point P17 (47.225, 137.2115)
  point P18 (43.225, 137.2115)
  midpoint L8 P10
  midpoint L6 P11
  midpoint L5 P12
  midpoint L7 P13
  midpoint L1 P14
  perpendicular L1 L11
  coincident P5 P16
  perpendicular L3 L12
  perpendicular L12 L13
  coincident L10 P20
  tangent L14 A2
  perpendicular L10 L14
  coincident L10 P22
  tangent L15 A2
  perpendicular L10 L15
  coincident P19 P24
  perpendicular L13 L16
  coincident P25 P26
  tangent L17 A1
  tangent L18 A1
  symmetric L9 P20 P29
  symmetric L9 P21 P30
  symmetric L9 P22 P33
  symmetric L9 P23 P32
  symmetric L9 P27 P36
  symmetric L9 P28 P34
  symmetric L9 A1 A4
  symmetric L9 A2 A3
  concentric A2 C1
  concentric A1 C2
  concentric A3 C3
  concentric A4 C4
  dimension "d650" distance P14 P15 = 10
  dimension "d651" distance P16 P17 = 23.27
  dimension "d652" distance P17 P18 = 4
  dimension "d655" diameter A2 = 3
  dimension "d690" distance P24 P25 = 10
  dimension "d691" diameter A1 = 3
  dimension "d692" diameter C1 = 3
  dimension "d693" diameter C2 = 3
  dimension "d694" diameter C3 = 3
  dimension "d695" diameter C4 = 3
extrude "Extrude2" cut sketch "Sketch3" profile of A2 A3 C1 C3 against normal blind 9
extrude "Extrude4" new body sketch "Sketch3" profile of L1 L2 L3 L4 L5 L6 L7 L8 L13 A2 L14 L15 A1 L17 L18 L19 A3 L20 L21 A4 L22 C1 C2 C3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 along normal blind 6 bodies "Motor_holder_wing"
move "Move6"
move "Move7"
move "Move2"
move "Move8"
move "Move1"
move "Move2"
move "Move9"
move "Move3"
move "Move10"
move "Move4"
move "Move1"
move "Move11"
move "Move3"
move "Move4"
extrude "Extrude4" add of existing geometry blind 1
extrude "Extrude5" add of existing geometry blind 1
extrude "Extrude6" add of existing geometry blind 1
extrude "Extrude4" add of existing geometry blind 1
extrude "Extrude2" add of existing geometry blind 18
extrude "Extrude3" add of existing geometry blind 1
move "Move1"
copy_paste_bodies "CopyPasteBodies1"
copy_paste_bodies "CopyPasteBodies2"
move "Move1"
move "Move2"
extrude "Extrude3" add of existing geometry blind 1
extrude "Extrude1" add of existing geometry blind 1
move "Move2"
extrude "Extrude4" add of existing geometry blind 1
extrude "Extrude5" cut of existing geometry blind -2
extrude "Extrude6" add of existing geometry blind 2
extrude "Extrude7" cut of existing geometry blind -4
extrude "Extrude8" cut of existing geometry blind -3
extrude "Extrude2" cut of existing geometry blind -1
move "Move3"
sketch "Sketch4" plane through (138, 0, 0) normal (1, 0, 0) x axis (0, 1, 0)
  circle C1 centre (-1.2, 70.6) radius 13.1
  circle C2 centre (-1.2, 70.6) radius 27.5
  concentric C1 C2
  dimension "d696" diameter C2 = 55
extrude "Extrude4" add sketch "Sketch4" along normal blind 10
extrude "Extrude5" add of existing geometry blind 10
component_from_bodies "Body->Comp1"
sketch "Sketch1" plane through (0, 0, 0) normal (0, 1, 0) x axis (1, 0, 0)
  line L1 (129, -345.8) -> (129, -315.8)
  line L2 (129, -315.8) -> (129, -305.8)
  line L3 (129, -305.8) -> (136, -305.8)
  line L4 (129, -355.8) -> (136, -355.8)
  line L5 (129, -355.8) -> (129, -345.8)
  line L6 (136, -355.8) -> (136, -360.8)
  line L7 (136, -300.8) -> (136, -305.8)
  line L8 (139, -360.8) -> (136, -360.8)
  line L9 (139, -300.8) -> (136, -300.8)
  line L10 (139, -300.8) -> (139, -315.8)
  line L11 (139, -315.8) -> (139, -345.8)
  line L12 (139, -345.8) -> (139, -360.8)
  line L13 (158, -168.5) -> (158, -196)
  line L14 (158, -196) -> (158, -223.5)
  line L15 (138, -168.5) -> (138, -182.9)
  line L16 (138, -209.1) -> (138, -223.5)
  line L17 (129, -182.9) -> (129, -196)
  line L18 (129, -196) -> (129, -209.1)
  line L19 (158, -223.5) -> (138, -223.5)
  line L20 (158, -168.5) -> (138, -168.5)
  line L21 (138, -209.1) -> (129, -209.1)
  line L22 (138, -182.9) -> (129, -182.9)
extrude "Extrude2" new body of existing geometry blind 9 bodies "Coil"
thread "Thread1" ThreadOffset 0 ThreadLength 10
fillet "Fillet1" radius 5
sketch "Sketch9" plane through (0, 0, 0) normal (1, 0, 0) x axis (0, 1, 0)
sketch "Test_Wall" plane through (-17, 0, 0) normal (-1, 0, 0) x axis (0, -1, 0)
  line L1 (-51, 105.9415) -> (-41, 105.9415)
  line L2 (-41, 170.1585) -> (-41, 105.9415)
  line L3 (-51, 105.9415) -> (-51, 170.1585)
  line L4 (-51, 170.1585) -> (-41, 170.1585)
  line L5 (25, 225) -> (-25, 225)
  line L6 (25, 50) -> (25, 225)
  line L7 (-25, 50) -> (25, 50)
  line L8 (-25, 225) -> (-25, 50)
  line L9 (-41, 180) -> (-51, 180)
  line L10 (-41, 96.1211) -> (-41, 180)
  line L11 (-51, 96.1211) -> (-41, 96.1211)
  line L12 (-51, 180) -> (-51, 96.1211)
  line L13 (-25, 170.1585) -> (-35.0171, 170.1585)
  line L14 (-25, 106) -> (-35, 106)
  circle C1 centre (0, 70.6) radius 13.1
  point P16 (-25, 170.1585)
  point P18 (-25, 106)
  horizontal L5
  vertical L6
  horizontal L7
  vertical L8
  horizontal L9
  vertical L10
  horizontal L11
  vertical L12
  coincident L8 P16
  perpendicular L8 L13
  coincident L8 P18
  perpendicular L8 L14
extrude "Extrude1" new body sketch "Test_Wall" profile of C1 L5 L6 L7 L8 along normal blind 1 and against normal blind 9 bodies "Motor_test_wall"
extrude "Extrude11" new body of existing geometry blind -9 bodies "Cutter_LU_Wall_Cap_"
extrude "Extrude5" new body of existing geometry blind -9 bodies "Cutter_sliding_cap"
extrude "Extrude12" new body of existing geometry blind -9 bodies "Cutter_LL_Wall_Cap"
combine "Combine1"
combine "Combine2"
extrude "Extrude2" new body of existing geometry blind 57
extrude "Extrude3" add of existing geometry blind 26
sketch "Sketch1" plane through (0, 51, 0) normal (0, 1, 0) x axis (-1, 0, 0)
  line L1 (-39.225, 170.1585) -> (8, 170.1585)
  line L2 (-39.225, 105.9415) -> (-39.225, 170.1585)
  line L3 (8, 105.9415) -> (-39.225, 105.9415)
  line L4 (8, 50) -> (8, 105.9415)
  line L5 (18, 50) -> (8, 50)
  line L6 (18, 225) -> (18, 50)
  line L7 (8, 225) -> (18, 225)
  line L8 (8, 170.1585) -> (8, 225)
  line L9 (18, 225) -> (8, 225)
  line L10 (18, 170.4172) -> (18, 225)
  line L11 (8, 170.4172) -> (18, 170.4172)
  line L12 (8, 225) -> (8, 170.4172)
  line L13 (18, 105.9415) -> (8, 105.9415)
  line L14 (18, 50) -> (18, 105.9415)
  line L15 (8, 50) -> (18, 50)
  line L16 (8, 105.9415) -> (8, 50)
  point P12 (18, 170.4172)
  point P9 (8, 225)
  point P10 (8, 225)
  point P7 (18, 50)
  point P16 (18, 50)
  point P5 (8, 105.9415)
  point P14 (8, 105.9415)
  horizontal L9
  vertical L10
  horizontal L11
  vertical L12
  coincident L6 P12
  coincident P9 P10
  horizontal L13
  vertical L14
  horizontal L15
  vertical L16
  coincident P7 P16
  coincident P5 P14
extrude "Extrude4" cut sketch "Sketch1" profile of L4 L5 L6 L13 L14 L15 L16 against normal blind 30
extrude "Extrude5" cut sketch "Sketch1" profile of L6 L7 L8 L9 L10 L11 L12 against normal blind 30
extrude "Extrude6" cut of existing geometry blind -5
combine "Combine3"
extrude "Extrude8" new body sketch "Sketch1" profile of C1 C2 C3 L1 L2 L3 L4 A1 A2 A3 A4 L9 L8 A8 L7 A9 L11 L10 A10 A6 C4 C5 C6 C7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 along normal blind 4 bodies "Cutter_exterior"
extrude "Extrude9" new body sketch "Sketch1" profile of C1 C2 C3 L1 L2 L3 L4 A1 A2 A3 A4 L7 against normal blind 7 bodies "Cutter_interior"
combine "Combine1" bodies "Cutter_exterior"
work_plane "WorkPlane1" AlongDistance 0
sketch "Sketch1" plane through (-17, 0, 0) normal (-1, 0, 0) x axis (0, -1, 0)
  line L1 (-53, 142) -> (-51, 142)
  line L2 (150.2762, 237.3171) -> (-53, 292.6532)
  line L3 (150.5352, 231.8021) -> (151.5254, 235.0563)
  line L4 (-2.8201, 30) -> (-33, 30)
  line L5 (72.4247, 251.2552) -> (2.6295, 254.9308)
  line L6 (-53, 50) -> (-53, 142)
  line L7 (-53, 254.9308) -> (-53, 142)
  line L8 (-2.6295, 254.9308) -> (2.6295, 254.9308)
  line L9 (0, 254.9308) -> (-53, 254.9308)
  curve K1 (35.395, 253.2053) -> (39.3474, 235.851)
  curve K2 (37.4515, 238.4355) -> (41.2432, 233.2665)
  line L10 (-53, 285.3985) -> (-53, 254.9308)
  line L11 (-53, 292.6532) -> (-53, 285.3985)
  line L12 (148.3404, 230.5893) -> (-53, 285.3985)
  line L13 (60, 60) -> (60, 205)
  line L14 (51.9615, 175) -> (0, 205)
  line L15 (60, 205) -> (0, 205)
  line L16 (57.1799, 80) -> (-2.8201, 80)
  line L17 (57.1799, 80) -> (-2.8201, 80)
  line L18 (51.9615, 80) -> (51.9615, 175)
  line L19 (51.9615, 80) -> (-2.8201, 80)
  line L20 (-46, 254.9308) -> (-53, 254.9308)
  line L21 (-53, 254.9308) -> (-53, 50)
  line L22 (-53, 30) -> (-53, 50)
  line L23 (-33, 30) -> (-53, 30)
  line L24 (-60, 30) -> (-53, 30)
  line L25 (-60, 292.6532) -> (-60, 30)
  line L26 (-53, 292.6532) -> (-60, 292.6532)
  line L27 (-53, 30) -> (-53, 292.6532)
  line L28 (23, 170) -> (32, 170)
  line L29 (20, 187) -> (20, 173)
  line L30 (32, 190) -> (23, 190)
  line L31 (35, 173) -> (35, 187)
  line L32 (35, 80) -> (35, 170)
  line L33 (23, 80) -> (32, 80)
  line L34 (20, 63) -> (20, 77)
  line L35 (32, 60) -> (23, 60)
  line L36 (35, 77) -> (35, 63)
  line L37 (-60, 254.9308) -> (-53, 254.9308)
  circle C1 centre (0, 205) radius 50
  circle C2 centre (-2.8201, 80) radius 50
  circle C3 centre (1.7685, 134.8228) radius 30.3814
  arc A1 centre (149.8034, 235.5803) radius 1.8 clockwise from (150.2762, 237.3171) to (151.5254, 235.0563)
  arc A2 centre (148.8131, 232.3261) radius 1.8 clockwise from (150.5352, 231.8021) to (148.3404, 230.5893)
  arc A3 centre (32, 187) radius 3 clockwise from (32, 190) to (35, 187)
  arc A4 centre (23, 187) radius 3 clockwise from (20, 187) to (23, 190)
  arc A5 centre (23, 173) radius 3 clockwise from (23, 170) to (20, 173)
  arc A6 centre (32, 173) radius 3 clockwise from (35, 173) to (32, 170)
  arc A7 centre (32, 77) radius 3 clockwise from (32, 80) to (35, 77)
  arc A8 centre (32, 63) radius 3 clockwise from (35, 63) to (32, 60)
  arc A9 centre (23, 77) radius 3 clockwise from (20, 77) to (23, 80)
  arc A10 centre (23, 63) radius 3 clockwise from (23, 60) to (20, 63)
  point P6 (2.6295, 254.9308)
  point P7 (-2.8201, 30)
  point P11 (-53, 254.9308)
  point P14 (-2.6295, 254.9308)
  point P15 (0, 254.9308)
  point P16 (39.3474, 235.851)
  point P18 (41.2432, 233.2665)
  point P2 (0, 205)
  point P23 (0, 205)
  point P3 (-2.8201, 80)
  point P26 (-2.8201, 80)
  point P28 (-2.8201, 80)
  point P30 (51.9615, 80)
  point P31 (-2.8201, 80)
  point P17 (35.395, 253.2053)
  point P46 (35, 80)
  point P45 (35, 190)
  point P44 (20, 170)
  point P43 (35, 170)
  point P48 (35, 60)
  point P47 (20, 80)
  point P73 (-60, 254.9308)
  point P10 (60, 205)
  point P24 (51.9615, 175)
  point P38 (-46, 254.9308)
  point P39 (-53, 30)
  point P40 (-60, 30)
  horizontal L1
  coincident C1 P6
  horizontal L8
  coincident C2 P7
  tangent C2 L4
  tangent C1 L5
  perpendicular L4 L6
  coincident P11 L8
  perpendicular L7 L8
  coincident C1 P14
  midpoint L8 P15
  coincident C1 P16
  midpoint P16 K2
  coincident C1 P18
  perpendicular L9 L10
  parallel L10 L11
  horizontal L15
  coincident P2 P23
  horizontal L16
  coincident P3 P26
  horizontal L17
  coincident P3 P28
  coincident L16 P30
  perpendicular L16 L18
  coincident P3 P31
  perpendicular L18 L19
  tangent L2 A1
  tangent L3 A1
  tangent L12 A2
  tangent L3 A2
  equal A1 A2
  coincident L5 P17
  horizontal L20
  vertical L21
  horizontal L24
  vertical L25
  horizontal L26
  vertical L27
  horizontal L28
  vertical L29
  horizontal L30
  vertical L31
  coincident L17 P46
  horizontal L33
  vertical L34
  horizontal L35
  vertical L36
  coincident P45 L30
  coincident P45 L31
  tangent L30 A3
  tangent L31 A3
  tangent L29 A4
  tangent L30 A4
  coincident P44 L28
  coincident P44 L29
  tangent L28 A5
  tangent L29 A5
  coincident P43 L31
  coincident P43 L28
  tangent L31 A6
  tangent L28 A6
  coincident P46 L33
  coincident P46 L36
  tangent L33 A7
  tangent L36 A7
  coincident P48 L36
  coincident P48 L35
  tangent L36 A8
  tangent L35 A8
  coincident P47 L33
  coincident P47 L34
  tangent L33 A9
  tangent L34 A9
  tangent L34 A10
  tangent L35 A10
  coincident L25 P73
  perpendicular L25 L37
  dimension "d740" diameter C1 = 100
  dimension "d741" diameter C2 = 100
  dimension "d761" distance P2 P10 = 60
  dimension "d763" distance P23 P24 = 60
  dimension "d764" angle L14 L15 = 30
  dimension "d771" radius A1 = 1.8
  dimension "d780" distance P11 P38 = 7
  dimension "d805" distance P39 P40 = 7
  dimension "d879" distance P43 P44 = 15
  dimension "d880" distance P43 P45 = 20
  dimension "d881" distance P46 P47 = 15
  dimension "d882" distance P46 P48 = 20
  dimension "d883" radius A3 = 3
  dimension "d884" radius A4 = 3
  dimension "d885" radius A5 = 3
  dimension "d886" radius A6 = 3
  dimension "d887" radius A7 = 3
  dimension "d888" radius A8 = 3
  dimension "d889" radius A9 = 3
  dimension "d890" radius A10 = 3
extrude "Extrude3" new body sketch "Sketch1" profile of C1 C2 L8 L4 L5 C3 L6 L7 L9 K1 L20 L21 L22 L23 L27 along normal blind 7
fillet "Fillet6" radius 50
extrude "Extrude4" new body sketch "Sketch1" profile of C1 L2 L12 L3 L5 L9 L10 L11 A1 A2 L20 L27 against normal blind 149 and along normal blind 7 bodies "Roof"
position "Position21"
sketch "Sketch11" plane through (-13.1975, 0, 0) normal (1, 0, 0) x axis (0, -1, 0)
  line L1 (-52.3693, -255.1758) -> (-52.3693, -30.245)
  line L2 (-32.3693, -30.245) -> (-2.1894, -30.245)
  curve K1 (36.0257, -253.4503) -> (39.9781, -236.096)
  line L3 (36.0257, -253.4503) -> (3.2602, -255.1758)
  line L4 (-1.9988, -255.1758) -> (-52.3693, -255.1758)
  line L5 (-52.3693, -30.245) -> (-32.3693, -30.245)
  arc A1 centre (-2.1894, -80.245) radius 50 clockwise from (-2.1894, -30.245) to (40.2825, -106.6295)
  arc A2 centre (82.7543, -133.0139) radius 50 clockwise from (32.7706, -134.2915) to (40.2825, -106.6295)
  arc A3 centre (2.3992, -135.0677) radius 30.3814 clockwise from (32.7706, -134.2915) to (32.4457, -139.5658)
  arc A4 centre (81.8947, -146.9684) radius 50 clockwise from (41.2627, -176.1067) to (32.4457, -139.5658)
  arc A5 centre (0.6307, -205.245) radius 50 clockwise from (3.2602, -255.1758) to (-1.9988, -255.1758)
  arc A6 centre (0.6307, -205.245) radius 50 clockwise from (41.2627, -176.1067) to (39.9781, -236.096)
